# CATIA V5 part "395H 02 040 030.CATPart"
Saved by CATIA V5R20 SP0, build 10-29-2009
Part number: Part1
Source: Unknown
Bounding box of the stored display mesh (mm): x -22 to 22, y -22 to 22, z -16 to 16
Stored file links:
  C:\Users\Utente\Desktop\3D files 395H FORD\395H 02 040 030.CATPart
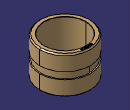
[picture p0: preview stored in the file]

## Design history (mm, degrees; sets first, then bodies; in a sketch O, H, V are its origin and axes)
Body1 (main body)
  Solid1 "PartBody": solid without history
